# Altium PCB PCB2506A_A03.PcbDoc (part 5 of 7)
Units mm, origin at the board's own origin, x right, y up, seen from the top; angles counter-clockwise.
Board outline 115 x 60 mm, 6 copper layers (Top Layer, Signal Layer 2, Signal Layer 3, Signal Layer 4, Signal Layer 5, Bottom Layer), stack 1.555 mm thick; 376 components, 290 nets, 1297 pads, 901 vias.
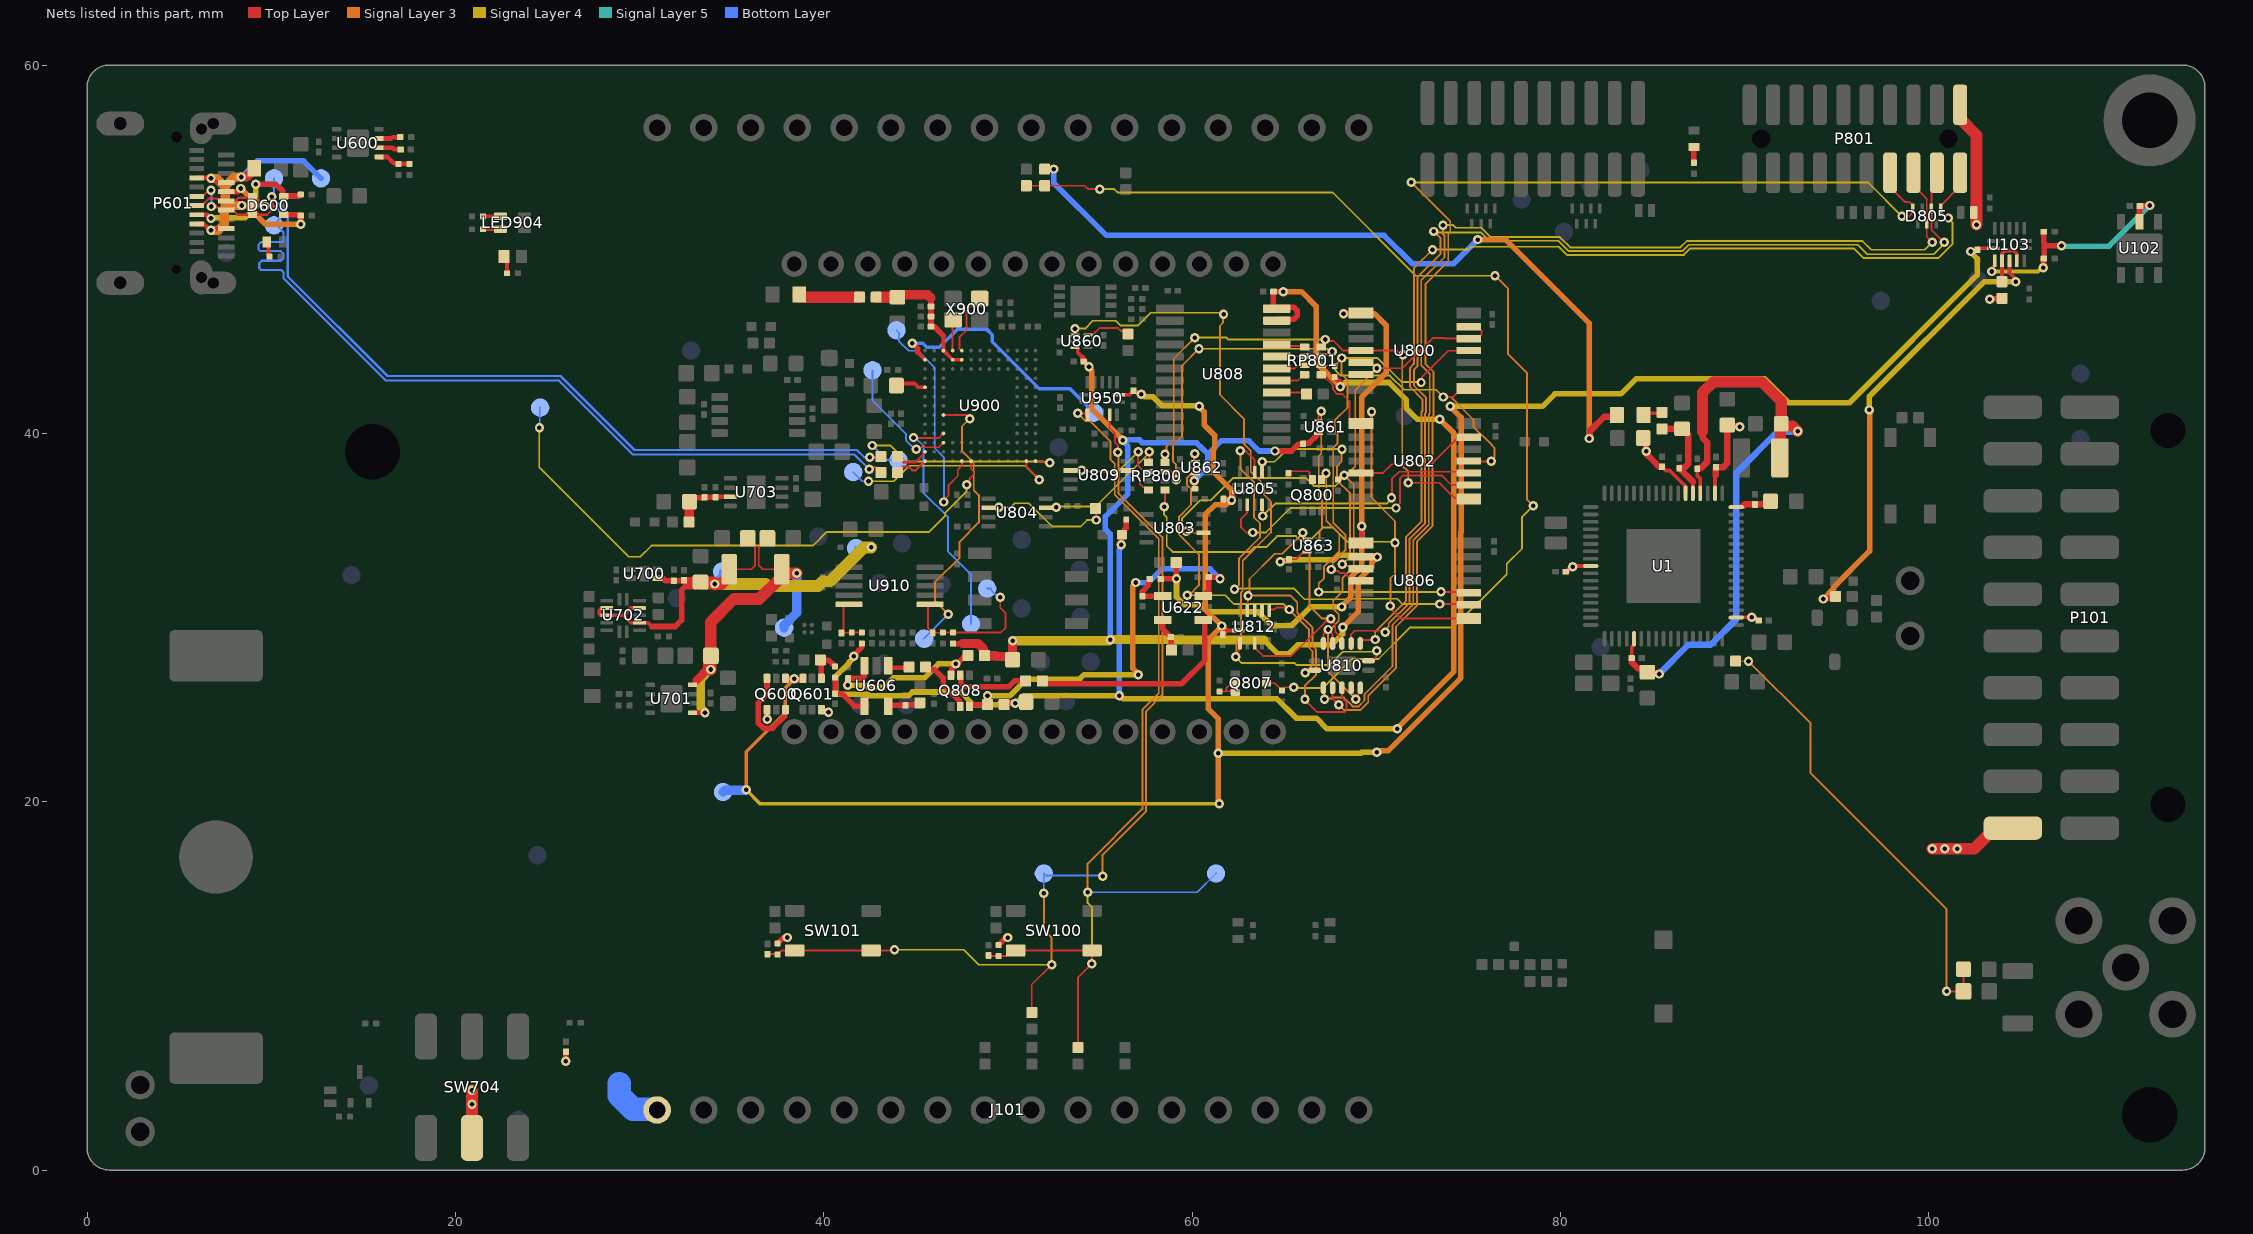
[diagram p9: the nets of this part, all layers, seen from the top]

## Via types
v1: diameter 0.508, hole 0.25, Top Layer to Bottom Layer, tented both sides, 901 vias

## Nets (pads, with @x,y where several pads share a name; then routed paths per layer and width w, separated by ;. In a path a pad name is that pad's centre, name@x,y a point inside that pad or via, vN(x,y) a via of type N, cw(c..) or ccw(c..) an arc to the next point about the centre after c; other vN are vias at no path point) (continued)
N16846319: Q800.1 U806.10 | length 15.8
  Top Layer w0.1: Q800.1@67.033,37.527 67.033,37.547 67.171,37.685 67.171,37.741 v1(67.276,37.846) ; v1(73.519,31.394) 74.981,31.394 U806.10@75.025,31.35
  Signal Layer 3 w0.1: v1(66.878,31.386) 66.878,31.855 67.169,32.146 67.169,32.778 67.996,33.604 67.996,34.541 67.286,35.25 67.286,37.836 v1(67.276,37.846)
  Signal Layer 4 w0.1: v1(66.878,31.386) 66.882,31.39 73.515,31.39 v1(73.519,31.394)
N16846537: RP801.5 U808.21 | length 1.6
  Top Layer w0.1: U808.21@64.6,44.825 64.671,44.754 66.056,44.754 RP801.5@66.118,44.692
N16846539: RP801.6 U808.20 | length 1.5
  Top Layer w0.1: U808.20@64.6,44.175 64.617,44.192 RP801.6@66.118,44.192
N16846547: RP801.7 U808.19 | length 1.6
  Top Layer w0.1: U808.19@64.6,43.525 65.575,43.525 65.718,43.668 66.094,43.668 RP801.7@66.118,43.692
N16846551: RP801.8 U808.18 | length 1.6
  Top Layer w0.1: U808.18@64.6,42.875 65.751,42.875 66.068,43.192 RP801.8@66.118,43.192
N16846567: Q800.2 R815.1 | length 1.6
  Top Layer w0.1: R815.1@65.232,37.832 65.232,37.838 65.342,37.948 66.312,37.948 66.371,37.889 66.371,37.725 66.533,37.563 Q800.2@66.533,37.527
N16846723: R805.1 U808.17 | length 1.7
  Top Layer w0.1: U808.17@64.6,42.225 64.607,42.218 66.147,42.218 R805.1@66.226,42.139
N16846896: RP800.8 U809.3 | length 1.8
  Top Layer w0.1: U809.3@56.498,37.985 56.573,37.91 56.883,37.91 57.161,37.631 57.161,37.276 57.359,37.078 57.482,37.078 RP800.8@57.632,36.928
N16846900: RP800.6 U809.6 | length 5.6
  Top Layer w0.1: U809.6@53.398,37.985 53.401,37.988 54.013,37.988 v1(54.016,37.992) ; v1(57.074,39.014) 57.074,38.252 57.318,38.008 57.552,38.008 RP800.6@57.632,37.928
  Signal Layer 4 w0.1: v1(54.016,37.992) 54.072,37.936 55.995,37.936 v1(57.074,39.014)
N16846924: RP800.5 U804.3 | length 7.5
  Top Layer w0.1: U804.3@52.053,35.954 52.073,35.973 52.608,35.973 v1(52.628,35.993) ; RP800.5@57.632,38.428 57.682,38.478 v1(57.682,39.008)
  Signal Layer 4 w0.1: v1(52.628,35.993) 52.666,36.031 54.776,36.031 57.682,38.937 v1(57.682,39.008)
N16847739: U805.10 U806.9 | length 23.3
  Top Layer w0.1: v1(62.625,39.068) 62.9,39.068 63.4,38.568 U805.10@63.4,37.885 ; v1(73.457,30.734) 74.991,30.734 U806.9@75.025,30.7
  Signal Layer 3 w0.1: v1@62.309,31.55 62.554,31.795 62.554,33.217 63.69,34.353 63.69,35.116 63.373,35.433 63.373,37.338 62.625,38.086 v1(62.625,39.068)
  Signal Layer 4 w0.1: v1(62.306,31.547) 62.343,31.584 65.517,31.584 66.108,30.993 68.508,30.993 68.533,31.019 71.145,31.019 71.43,30.734 v1(73.457,30.734)
N16847741: U805.9 U806.3 | length 13.3
  Top Layer w0.1: v1(63.807,38.464) 63.804,38.461 63.804,37.798 U805.9@63.832,37.77 ; v1(68.154,32.887) 68.265,32.887 68.352,32.8 69.025,32.8 U806.3@69.175,32.65
  Signal Layer 3 w0.1: v1(68.146,39.146) 68.107,39.106 68.107,38.465 67.869,38.227 67.869,37.465 68.58,36.754 68.58,33.311 v1(68.154,32.887) v1(68.154,32.887)
  Signal Layer 4 w0.1: v1(63.807,38.464) 64.478,38.464 64.667,38.653 64.669,38.653 65.162,39.146 v1(68.146,39.146)
N16847743: U802.10 U805.4 | length 13.4
  Top Layer w0.1: U805.4@63.8,36.115 63.822,36.093 63.822,35.54 v1(63.843,35.518) ; v1(70.831,36.509) 70.854,36.531 70.854,37.529 71.246,37.921 74.954,37.921 U802.10@75.025,37.85
  Signal Layer 4 w0.1: v1(63.843,35.518) 64.515,36.19 70.576,36.19 70.831,36.445 v1(70.831,36.509)
N16847749: U802.9 U805.2 | length 16.4
  Top Layer w0.1: U805.2@63,36.355 62.99,36.345 62.99,35.685 62.662,35.357 62.662,34.9 62.941,34.62 v1(63.297,34.62) ; v1(71.074,35.951) 71.074,35.975 71.298,36.199 71.298,37.565 71.454,37.721 73.556,37.721 74.077,37.2 U802.9@75.025,37.2
  Signal Layer 4 w0.1: v1(63.297,34.62) 64.008,34.62 65.339,35.951 v1(71.074,35.951)
N16847975: R810.1 U804.6 | length 7.3
  Top Layer w0.1: U804.6@48.953,35.954 48.971,35.972 49.5,35.972 v1(49.518,35.99) ; R810.1@54.75,35.925 54.8,35.875 v1(54.8,35.3)
  Signal Layer 3 w0.1: v1(54.8,35.3) v1@54.825,35.3
  Signal Layer 4 w0.1: v1(49.518,35.99) 50.155,35.99 50.372,36.207 51.144,36.207 52.406,34.945 53.946,34.945 54.301,35.3 v1(54.8,35.3)
N16851964: C127.2 R128.2 R129.1 | length 25.2
  Top Layer w0.1: R129.1@89.523,27.638 89.537,27.624 v1(90.215,27.624) ; v1(100.972,9.7) R128.2@101.889,9.7 C127.2@101.889,10.9
  Signal Layer 3 w0.1: v1(90.215,27.624) 93.586,24.253 93.586,21.554 100.972,14.168 v1(100.972,9.7)
N16916520: U810.1 U812.1 U860.4 | length 39.6
  Top Layer w0.1: U860.4@53.5,45.35 53.62,45.35 53.645,45.375 v1(53.645,45.695) ; v1(62.372,27.868) 62.45,27.946 62.45,28.098 62.563,28.212 62.563,28.578 U812.1@62.6,28.615 ; U810.1@69.585,27.643 69.785,27.643 70.007,27.865 70.007,28.187 v1(70.024,28.204)
  Signal Layer 3 w0.1: v1(61.711,46.471) 61.678,46.437 61.678,46.006 61.519,45.847 61.519,42.099 62.817,40.8 62.817,39.431 63.189,39.059 63.189,37.928 63.906,37.21 63.906,36.667 64.287,36.286 64.287,34.626 62.754,33.093 62.754,31.458 62.65,31.354 62.65,28.843 62.409,28.601 62.409,27.905 v1(62.372,27.868)
  Signal Layer 4 w0.1: v1(53.645,45.695) 54.195,45.695 54.618,46.118 55.867,46.118 56.131,45.854 57.055,45.854 57.751,46.55 61.449,46.55 61.45,46.549 61.633,46.549 v1(61.711,46.471) ; v1(62.372,27.868) 62.372,27.86 62.707,27.524 65.575,27.524 65.667,27.432 67.474,27.432 68.185,28.143 69.964,28.143 v1(70.024,28.204)
N16916530: U810.4 U812.3 U861.4 | length 20
  Top Layer w0.1: U812.3@63.4,28.615 63.4,28.375 63.55,28.225 ; 63.55,28.225 63.86,27.915 65.383,27.915 67.223,29.755 67.234,29.755 67.351,29.873 67.463,29.873 67.466,29.87 67.615,29.87 67.615,29.777 67.779,29.613 67.779,29.227 68.062,28.944 68.062,28.921 68.135,28.847 U810.4@68.135,28.593 ; U861.4@66.873,40.693 66.873,40.958 67.013,41.098 v1(67.013,41.209) ; v1(67.529,29.942) v1@67.6,29.87
  Signal Layer 3 w0.1: v1(67.013,41.209) 67.013,38.891 66.883,38.761 66.883,36.574 67.056,36.401 67.056,34.849 66.924,34.717 66.924,34.26 66.384,33.719 66.384,30.619 67.061,29.942 v1(67.529,29.942)
N16916558: U810.11 U812.11 U863.4 | length 19
  Top Layer w0.1: U812.11@63,30.385 63.021,30.406 63.021,31.17 v1(63.043,31.191) ; v1(66.015,34.612) 66.036,34.59 66.036,34.288 66.061,34.263 U863.4@66.236,34.263 ; v1(66.131,25.571) 66.131,25.537 66.802,24.867 68.298,24.867 68.389,24.957 68.389,25.41 68.135,25.664 U810.11@68.135,26.193
  Signal Layer 3 w0.1: v1(66.015,34.612) 66.015,34.575 64.903,33.464 64.489,33.464 63.121,32.096 63.121,31.269 v1(63.043,31.191) 65.352,31.191 65.715,30.829 65.715,30.268 66.545,29.438 66.545,28.457 66.734,28.267 66.734,26.907 66.131,26.304 v1(66.131,25.571)
N16916616: U810.8 U812.8 U862.4 | length 21.1
  Top Layer w0.1: v1(60.139,38.887) 60.139,38.51 60.146,38.503 U862.4@60.173,38.503 ; U812.8@64.2,30.385 64.25,30.435 64.25,30.441 64.471,30.441 64.572,30.543 65.061,30.543 65.164,30.44 v1(65.272,30.44) ; v1(66.153,27.007) 66.264,27.007 66.362,27.105 66.647,27.105 U810.8@66.685,27.143
  Signal Layer 3 w0.1: v1(59.746,31.217) 59.846,31.217 60.376,31.747 60.376,33.426 59.297,34.505 59.297,35.484 59.819,36.005 59.944,36.131 59.944,36.982 59.81,37.116 59.729,37.197 59.729,37.602 60.096,37.97 60.096,38.844 v1(60.139,38.887) ; v1(65.272,30.44) 65.272,30.428 66.345,29.355 66.345,28.374 66.534,28.184 66.534,27.4 66.153,27.019 v1(66.153,27.007)
  Signal Layer 4 w0.1: v1(59.746,31.217) 61.795,31.217 62.277,30.734 64.978,30.734 v1(65.272,30.44)
N16917071: R882.1 U860.3 | length 2.5
  Top Layer w0.1: U860.3@54.35,45.35 54.375,45.375 54.646,45.375 54.996,45.725 55.977,45.725 56.134,45.568 56.357,45.568 R882.1@56.525,45.4
N16922979: R601.1 R602.2 U600.5 | length 1.8
  Top Layer w0.25: U600.5@15.85,55.013 16.31,55.013 16.643,54.68 16.865,54.68 R601.1@16.9,54.645 ; R601.1@16.9,54.635 R602.2@17.5,54.635
N16923003: R600.1 U600.7 | length 1.2
  Top Layer w0.25: U600.7@15.85,56.013 16.516,56.013 16.59,56.087 R600.1@17,56.087
N16923019: C602.1 U600.6 | length 1.2
  Top Layer w0.25: U600.6@15.85,55.513 16.598,55.513 16.689,55.422 17.014,55.422 C602.1@17.025,55.411
N16924927: Q600.3 Q600.6 | length 4.9
  Top Layer w0.3: Q600.6@36.919,26.7 36.919,25.845 36.439,25.364 36.439,24.281 36.727,23.993 37.226,23.993 37.882,24.648 Q600.3@37.882,25.053
N16934878: C900.1 U900.J13 | length 1.7
  Top Layer w0.2: C900.1@43.95,42.6 44.057,42.707 44.939,42.707 45.146,42.5 U900.J13@45.5,42.5
N16934900: C903.1 C904.1 C905.1 C906.1 R130.2 U900.M9 U900.M10 U900.N11 | length 7.5
  Top Layer w0.2: 46.5,45.3 U900.N11@46.5,44.5 U900.M10@47,44 U900.M9@47.5,44
  Top Layer w0.3: 45.825,47.35 C906.1@45.825,46.9 C905.1@45.825,46.35 C904.1@45.825,45.8 46,45.8 46.5,45.3
  Top Layer w0.5: C903.1@44,47.4 44.125,47.525 45.65,47.525 45.825,47.35
  Top Layer w0.635: R130.2@42.85,47.4 C903.1@44,47.4
N16936696: U900.N10 X900.1 | length 1.7
  Top Layer w0.1: U900.N10@47,44.5 47,46.15 X900.1@47.05,46.2
N16936699: U900.N9 X900.3 | length 3.2
  Top Layer w0.1: U900.N9@47.5,44.5 47.48,44.5 47.371,44.609 47.371,45.212 47.752,45.593 47.752,46.652 X900.3@48.3,47.2
N16938060: TPJ905.1 U900.M13 | length 13.7
  Top Layer w0.2: 45.1,44.4 U900.M13@45.5,44
  Top Layer w0.3: v1(44.8,44.9) 45.1,44.6 45.1,44.4
  Bottom Layer w0.2: v1(44.8,44.9) 45.374,44.9 45.595,44.679 46.279,44.679 47.249,45.649 48.865,45.649 49.149,45.364 49.149,44.983 51.707,42.425 53.379,42.425 TPJ905.1@54.678,41.126
N16939106: TPJ909.1 U900.C11 | length 6.7
  Top Layer w0.1: v1@45.25,39.25 46.25,39.25 U900.C11@46.5,39.5
  Bottom Layer w0.1: TPJ909.1@42.651,43.427 42.651,41.774 44.475,39.95 44.475,39.656 44.482,39.649 44.482,39.612 44.944,39.15 v1(45.025,39.15)
N16939109: TPJ910.1 U900.D11 | length 13.2
  Top Layer w0.1: v1(44.875,39.775) 44.9,39.75 46.25,39.75 U900.D11@46.5,40
  Bottom Layer w0.1: v1(44.875,39.775) 44.975,39.775 45.418,39.332 45.418,38.368 45.415,38.365 45.415,36.785 46.75,35.45 46.75,33.579 48.003,32.326 TPJ910.1@48.003,29.65
N16939489: TPJ911.1 U900.F11 | length 15.8
  Top Layer w0.1: U900.F11@46.5,41 47.725,41 v1(47.925,40.8)
  Signal Layer 3 w0.1: v1(46.761,30.175) 46.05,30.886 46.05,31.935 47.375,33.26 47.375,34.119 48.424,35.169 48.424,36.649 48.15,36.923 48.15,38.404 47.5,39.054 47.5,40.375 v1(47.925,40.8)
  Bottom Layer w0.1: TPJ911.1@45.453,28.85 45.453,28.867 v1(46.761,30.175)
N16939638: TPJ900.1 U900.A2 | length 12.3
  Top Layer w0.1: U900.A2@51,38.5 51.019,38.481 51.019,38.188 51.488,37.719 51.562,37.719 51.706,37.575 v1(51.706,37.477)
  Signal Layer 4 w0.1: v1(42.429,37.4) 43.8,37.4 44.646,38.246 50.937,38.246 v1(51.706,37.477)
  Bottom Layer w0.1: TPJ900.1@41.602,37.9 42.102,37.4 v1(42.429,37.4)
N16939640: TPJ901.1 U900.A1 | length 12.6
  Top Layer w0.1: U900.A1@51.5,38.5 51.519,38.481 51.59,38.481 51.592,38.478 51.922,38.478 51.922,38.476 52.019,38.379 52.255,38.379 v1(52.278,38.403)
  Signal Layer 4 w0.1: v1(42.631,39.346) 43.604,39.346 44.473,38.477 51.921,38.477 51.951,38.447 52.234,38.447 v1(52.278,38.403)
  Bottom Layer w0.1: v1(42.631,39.346) 43.426,38.55 TPJ901.1@44.053,38.55
N16940103: TPJ908.1 U900.A9 | length 13.3
  Top Layer w0.1: v1(46.525,36.275) 46.525,36.376 46.782,36.633 46.782,37.196 47.275,37.688 47.275,38.016 47.5,38.241 U900.A9@47.5,38.5
  Bottom Layer w0.1: TPJ908.1@43.952,45.601 44.085,45.468 44.085,45.015 44.607,44.493 45.107,44.493 46.025,43.575 46.025,39.208 46.525,38.708 v1(46.525,36.275)
N16942491: R902.2 U900.B13 | length 1.9
  Top Layer w0.12: R902.2@44,38.75 44.32,38.43 44.98,38.43 45.5,38.95 U900.B13@45.5,39
N16942503: R904.2 U900.A13 | length 1.9
  Top Layer w0.12: R904.2@44,37.875 44.325,38.2 44.6,38.2 44.8,38 45,38 U900.A13@45.5,38.5
N16943456: TPJ902.1 U900.A8 | length 31.9
  Top Layer w0.1: v1(47.757,37.209) 47.757,37.319 47.95,37.512 47.95,37.58 48.143,37.773 48.143,37.931 48,38.073 U900.A8@48,38.5
  Signal Layer 4 w0.1: v1(24.562,40.31) 24.551,40.299 24.551,38.173 29.419,33.306 30.044,33.306 30.647,33.909 39.416,33.909 40.157,34.65 45.721,34.65 46.6,35.529 46.6,35.7 47.757,36.857 v1(47.757,37.209)
  Bottom Layer w0.1: v1(24.562,40.31) 24.581,40.329 24.581,41.381 TPJ902.1@24.6,41.4
N16944010: LED903.2 R912.2 | length 1.1
  Top Layer w0.2: LED903.2@22.582,49.703 22.801,49.484 R912.2@22.801,48.688
N16996446: Q807.5 Q807.6 R838.1 | length 1.7
  Top Layer w0.1: R838.1@61.5,25.987 61.516,26.003 61.854,26.003 ; Q807.6@62.35,25.938 62.285,26.003 61.854,26.003 ; Q807.5@62.35,26.438 62.212,26.3 61.987,26.3 61.854,26.167 61.854,26.003
N17012885: L900.2 R130.1 | length 3.5
  Top Layer w0.635: L900.2@38.615,47.55 38.615,47.445 38.633,47.427 38.977,47.427 39.004,47.4 R130.1@41.95,47.4
N17065843: C15.1 C16.1 U1.51 | length 1.7
  Top Layer w0.2: C16.1@91.246,36.144 C16.1@91.418,36.316
  Top Layer w0.35: 89.971,36.075 89.937,36.075 90.005,36.143 C15.1@90.552,36.143 ; C15.1@90.507,36.144 C16.1@91.246,36.144
N17240604: LED904.2 R920.2 | length 0.9
  Top Layer w0.2: R920.2@21.501,51.789 LED904.2@22.451,51.789
N17240606: LED904.1 R919.2 | length 0.9
  Top Layer w0.2: R919.2@21.46,51.079 LED904.1@22.41,51.079
N17240618: LED901.1 R903.2 | length 0.9
  Top Layer w0.2: LED901.1@9.75,50.4 9.85,50.3 9.85,49.65 R903.2@9.9,49.6
N17240622: LED900.1 R900.2 | length 0.8
  Top Layer w0.3: R900.2@87.25,54.703 LED900.1@87.25,55.55
N17258791: C17.1 C18.1 R2.2 U1.56 | length 5.4
  Top Layer w0.2: U1.56@87.2,36.75 87.2,37.369
  Top Layer w0.35: R2.2@85.522,40.248 85.526,40.251 86.604,40.251 C17.1@86.608,40.255 86.633,40.255 86.944,39.943 86.944,38.339 86.739,38.134 86.547,38.134 C18.1@86.496,38.084 ; C18.1@86.455,38.114 87.2,37.369
N17258819: L1.2 R2.1 | length 1
  Top Layer w0.2: L1.2@84.587,40.972 84.712,41.097 R2.1@85.522,41.097
N17457277: R984.2 U103.2 U103.4 | length 2.9
  Top Layer w0.2: R984.2@103.981,48.237 103.988,48.244 U103.2@103.988,49.366 103.988,49.759 104.165,49.936 104.615,49.936 104.788,49.764 U103.4@104.788,49.366
N17523909: Q808.6 R674.1 R675.1 U606.3 | length 9.6
  Top Layer w0.3: v1(41.313,26.319) R674.1@41.313,26.7 42.092,26.7 42.211,26.819 U606.3@42.211,27.392 ; Q808.6@46.915,26.869 46.953,26.907 46.953,27.212 47.168,27.427 v1(47.168,27.483) 47.224,27.483 R675.1@47.606,27.865
  Signal Layer 4 w0.3: v1(41.313,26.319) 42.273,26.319 42.366,26.226 43.269,26.226 43.774,26.731 45.476,26.731 46.228,27.483 v1(47.168,27.483)
N17523935: Q808.2 R679.2 | length 3.1
  Top Layer w0.3: R679.2@45.529,27.315 45.679,27.165 46.035,27.165 46.478,26.722 46.478,26.543 46.482,26.539 46.482,26.366 47.353,25.496 47.353,25.43 47.378,25.405 47.378,25.269 Q808.2@47.411,25.237
N17523983: Q601.4 R628.1 R672.2 | length 1.9
  Top Layer w0.3: R628.1@39.819,27.7 39.869,27.65 Q601.4@39.869,26.7 ; R628.1@39.869,27.737 39.916,27.69 40.269,27.69 40.599,27.36 40.609,27.36 40.619,27.35 R672.2@40.619,27.34
N17523989: C621.1 R672.1 U606.4 | length 2.8
  Top Layer w0.25: R672.1@40.619,26.74 40.619,26.75 R672.1@40.654,26.785
  Top Layer w0.3: R672.1@40.619,26.74 C621.1@40.619,25.865 40.987,25.865 41.661,25.192 U606.4@42.211,25.192
N17524020: R679.1 U606.1 | length 1.1
  Top Layer w0.25: U606.1@43.511,27.242 43.548,27.279 44.592,27.279 R679.1@44.629,27.315
N17524076: C660.1 R681.1 U606.5 | length 1.9
  Top Layer w0.3: U606.5@43.511,25.342 43.511,25.284 43.561,25.234 C660.1@44.44,25.234 44.44,25.254 44.45,25.264 45.11,25.264 R681.1@45.216,25.37
N17524925: Q808.3 R687.1 R688.1 U622.3 | length 22.3
  Top Layer w0.3: Q808.3@47.915,25.169 47.915,25.232 47.953,25.269 48.123,25.269 48.129,25.275 R687.1@48.896,25.275 v1(48.896,25.755) ; U622.3@60.6,31.171 60.904,31.476 R688.1@60.904,32.2 61.424,32.2 v1(61.519,32.106)
  Signal Layer 3 w0.3: v1(56.947,31.902) 56.769,31.725 56.769,27.26 57.074,26.955 v1(57.074,26.899)
  Signal Layer 4 w0.3: v1(48.896,25.755) 50.108,25.755 51.013,26.66 53.896,26.66 54.135,26.899 v1(57.074,26.899)
  Bottom Layer w0.3: v1(56.947,31.902) 57.633,31.902 58.369,32.639 60.985,32.639 v1(61.519,32.106)
N17524951: Q808.5 R686.2 | length 4.2
  Top Layer w0.3: Q808.5@47.415,26.869 47.434,26.851 47.434,26.441 47.627,26.248 50.056,26.248 50.367,26.559 R686.2@50.968,26.559
N17524994: C653.1 R629.1 U622.4 | length 2.2
  Top Layer w0.3: R629.1@57.7,32.1 57.7,31.97 57.633,31.902 57.633,31.761 57.3,31.428 C653.1@57.3,31.161 58.39,31.161 U622.4@58.4,31.171
N17525025: R686.1 U622.1 | length 11.6
  Top Layer w0.3: R686.1@51.868,26.559 52.018,26.409 52.19,26.409 52.194,26.406 59.426,26.406 60.693,27.673 U622.1@60.693,29.871
N17525073: C652.1 R690.1 U622.5 | length 1.9
  Top Layer w0.3: U622.5@58.4,29.871 58.419,29.852 58.419,29.372 58.817,28.975 58.817,28.955 58.827,28.945 58.856,28.945 58.866,28.935 58.866,28.248 R690.1@58.885,28.228
SI_HEADER_ENABLE: R807.2 U800.5 U800.6 U800.12 U800.13 U802.5 U802.13 U803.6 U810.5 U810.6 U810.12 U810.13 | length 53.2
  Top Layer w0.1: v1(59.69,34.696) 59.787,34.599 U803.6@60.621,34.599 ; U810.6@67.135,28.593 67.135,29.086 v1@67.386,29.337 ; v1(67.386,29.351) v1@67.386,29.337 ; U810.5@67.635,28.593 67.635,29.088 v1@67.386,29.337 ; R807.2@67.92,37.494 67.92,37.504 68.03,37.614 68.146,37.614 v1(68.262,37.73) 69.055,37.73 U802.5@69.175,37.85 70.362,37.85 70.84,38.329 73,38.329 74.321,39.65 74.875,39.65 U802.13@75.025,39.8 ; U810.12@68.635,26.193 68.635,25.939 v1@68.885,25.689 ; v1(68.885,25.571) v1@68.885,25.689 ; U810.13@69.135,26.193 69.135,25.939 v1@68.885,25.689 ; U800.6@69.175,43.2 69.65,43.2 69.929,43.479 v1@70.098,43.479 ; U800.5@69.175,43.85 69.325,43.7 69.896,43.7 69.917,43.679 70.012,43.679 v1@70.155,43.536 ; v1(70.041,43.536) v1@70.098,43.479 ; U800.13@75.025,45.8 75.5,45.8 75.717,45.583 75.717,45.367 75.587,45.237 75.112,45.237 U800.12@75.025,45.15 73.743,45.15 73.719,45.173 73.062,45.173 71.425,43.536 v1@70.155,43.536 ; v1@70.098,43.479 v1@70.155,43.536
  Signal Layer 3 w0.1: v1(68.885,25.571) 67.386,27.07 v1(67.386,29.351) 67.493,29.351 67.97,29.828 67.97,30.175 67.67,30.475 67.67,30.917 68.165,31.412 68.165,32.145 68.783,32.763 68.783,37.208 v1(68.262,37.73) 68.372,37.73 68.859,38.217 68.859,42.354 v1(70.041,43.536)
  Signal Layer 4 w0.1: v1(59.69,34.696) 59.69,34.728 59.461,34.956 59.461,35.382 60.452,36.373 61.008,36.373 62.211,37.576 66.192,37.576 66.631,37.137 67.764,37.137 68.262,37.634 v1(68.262,37.73)
SI_VCOM_CTS: D805.4 P801.8 U810.10 | length 65.2
  Top Layer w0.1: U810.10@67.635,26.193 67.635,25.586 v1(67.962,25.259) ; P801.8@97.905,54.158 97.905,53.37 98.7,52.575 98.95,52.575 99.15,52.375 D805.4@99.15,52.215 99.15,52 98.95,51.8 v1(98.55,51.8)
  Signal Layer 3 w0.1: v1(67.962,25.259) 67.984,25.259 68.265,24.978 69.13,24.978 69.566,25.414 69.566,25.748 71.085,27.266 71.085,29.516 72.214,30.645 72.214,34.12 73.055,34.96 73.055,40.92 73.112,40.977 73.112,43.347 72.669,43.79 72.669,48.108 73.911,49.349 73.911,50.826 74.022,50.937 74.022,51.53 v1(71.907,53.645)
  Signal Layer 4 w0.1: v1(71.907,53.645) 71.927,53.625 96.725,53.625 v1(98.55,51.8)
SI_VCOM_RTS: D805.6 P801.6 U810.9 | length 62.8
  Top Layer w0.1: U810.9@67.126,26.003 67.164,25.965 67.164,25.6 v1(67.194,25.571) ; P801.6@99.175,54.158 99.175,53.475 99.9,52.75 D805.6@99.9,51.385 99.9,50.675 v1(100.2,50.375)
  Signal Layer 3 w0.1: v1(67.194,25.571) 67.225,25.602 67.598,25.602 67.648,25.652 68.248,25.652 68.722,25.178 69.048,25.178 69.366,25.497 69.366,25.83 70.885,27.349 70.885,29.599 72.014,30.728 72.014,34.202 72.855,35.043 72.855,41.003 72.912,41.06 72.912,43.239 72.447,43.704 72.447,48.317 73.711,49.581 73.711,50.724 73.629,50.805 v1(73.629,51.311)
  Signal Layer 4 w0.1: v1(73.629,51.311) 74.176,51.311 74.318,51.169 75.711,51.169 76.219,50.66 79.966,50.66 80.529,50.098 86.521,50.098 86.874,50.45 96.4,50.45 96.875,49.975 99.8,49.975 v1(100.2,50.375)
SI_VCOM_RXD: D805.1 P801.2 U810.2 | length 57.8
  Top Layer w0.1: U810.2@69.135,28.593 69.135,28.643 69.227,28.735 69.227,28.775 69.913,28.775 v1(69.945,28.807) ; v1(101.075,51.7) 101,51.7 100.65,52.05 D805.1@100.65,52.215 100.65,52.375 101.715,53.44 P801.2@101.715,54.158
  Signal Layer 3 w0.1: v1(69.945,28.807) 69.945,29.226 70.322,29.603 71.614,30.894 71.614,34.368 72.455,35.209 72.455,41.169 72.512,41.226 72.512,41.853 71.844,42.52 71.844,43.571 72.047,43.774 72.047,48.972 v1(73.058,49.983)
  Signal Layer 4 w0.1: v1(73.058,49.983) 74.984,49.983 75.135,50.134 79.914,50.134 80.35,49.698 86.706,49.698 87.053,50.045 95.93,50.045 96.447,49.528 100.539,49.528 101.303,50.293 101.303,51.439 101.075,51.667 v1(101.075,51.7)
SI_VCOM_TXD: D805.2 P801.4 U810.3 | length 59.2
  Top Layer w0.1: U810.3@68.635,28.593 68.635,29.087 68.834,29.286 70.409,29.286 v1(70.485,29.21) ; P801.4@100.445,54.158 100.15,53.863 D805.2@100.15,52.215 100.15,51.05 100.811,50.389 v1(100.843,50.389)
  Signal Layer 3 w0.1: v1(70.485,29.21) 70.485,29.32 70.685,29.52 70.685,29.682 71.814,30.811 71.814,34.285 72.655,35.126 72.655,41.086 72.712,41.143 72.712,41.936 72.044,42.603 72.044,43.469 72.247,43.672 72.247,48.498 73.5,49.751 73.5,50.596 v1(73.127,50.969)
  Signal Layer 4 w0.1: v1(73.127,50.969) 73.178,50.918 74.495,50.918 74.497,50.92 75.677,50.92 76.136,50.46 79.883,50.46 80.446,49.898 86.623,49.898 86.97,50.245 96.155,50.245 96.672,49.728 100.278,49.728 100.843,50.293 v1(100.843,50.389)
TCK_SWCLK: RP800.3 RP801.3 U800.8 U802.11 | length 32
  Top Layer w0.1: RP800.3@58.532,37.928 58.897,37.928 59.058,37.767 59.058,37.563 v1(59.136,37.485) ; RP801.3@67.018,44.192 67.118,44.292 67.346,44.292 67.504,44.45 v1(67.615,44.45) ; v1(73.64,41.98) 74.18,41.98 74.65,42.45 U800.8@75.025,42.45 ; U802.11@75.025,38.5 75.044,38.481 v1(76.246,38.481)
  Signal Layer 3 w0.1: v1(59.136,37.485) 59.136,38.302 58.961,38.477 58.961,39.348 59.461,39.848 59.461,43.688 v1(60.376,44.602) ; v1(73.64,41.98) 74.057,41.98 75.282,40.756 75.282,40.357 76.291,39.348 76.291,39.344 76.429,39.206 76.429,38.744 76.246,38.561 v1(76.246,38.481)
  Signal Layer 4 w0.1: v1(60.376,44.602) 67.352,44.602 67.504,44.45 v1(67.615,44.45) 67.586,44.421 67.586,43.644 68.087,43.143 70.743,43.143 71.513,42.373 73.248,42.373 v1(73.64,41.98)
TDI: RP800.1 RP801.1 U802.1 U806.8 | length 37.7
  Top Layer w0.1: v1(58.499,36.013) 58.532,36.046 RP800.1@58.532,36.928 ; RP801.1@67.018,43.192 67.068,43.192 67.658,42.603 67.658,42.369 67.888,42.139 68.17,42.139 68.55,41.759 68.55,40.8 68.8,40.55 U802.1@69.175,40.55 69.327,40.702 69.651,40.702 69.748,40.8 v1(69.748,41.173) ; v1(70.771,30.626) 70.771,30.516 71.187,30.099 71.187,30.091 71.329,29.95 U806.8@75.025,29.95
  Signal Layer 3 w0.1: v1(69.748,41.173) 69.748,36.503 71.021,35.231 71.021,34.135 v1@71.095,34.061 ; v1(70.771,30.626) 70.778,30.634 70.778,32.145 71.021,32.387 71.021,33.988 v1@71.095,34.061 ; v1(71.021,34.061) v1@71.095,34.061
  Signal Layer 4 w0.1: v1(58.499,36.013) 58.471,35.985 58.471,35.611 58.623,35.458 58.623,33.888 58.944,33.567 63.125,33.567 63.388,33.83 64.026,33.83 64.621,34.425 65.645,34.425 65.923,34.148 66.355,34.148 67.094,34.886 67.668,34.886 68.437,34.118 70.964,34.118 v1(71.021,34.061)
TDO_SWO: R801.1 RP801.2 U800.11 U806.4 | length 24.2
  Top Layer w0.1: RP801.2@67.018,43.692 67.031,43.679 67.739,43.679 R801.1@67.752,43.667 67.752,43.677 68.123,44.047 v1(68.123,44.094) ; v1(67.562,32.614) 67.64,32.536 67.921,32.536 68.031,32.426 68.274,32.426 68.7,32 U806.4@69.175,32 ; v1(72.437,42.766) 72.494,42.823 72.494,43.081 73.903,44.49 75.015,44.49 U800.11@75.025,44.5
  Signal Layer 3 w0.1: v1(67.562,32.614) 67.64,32.692 67.64,32.966 68.326,33.652 68.326,34.493 67.669,35.151 67.669,39.224 67.906,39.461 67.906,40.007 67.753,40.16 67.753,40.705 68.443,41.396 68.443,42.885 68.123,43.205 v1(68.123,44.094)
  Signal Layer 4 w0.1: v1(68.123,44.094) 70.075,44.094 71.374,42.795 72.408,42.795 v1(72.437,42.766)
TMS_SWDIO: RP800.4 RP801.4 U800.4 U802.8 | length 30.5
  Top Layer w0.1: RP800.4@58.532,38.428 v1(58.532,38.872) ; RP801.4@67.018,44.692 67.058,44.692 67.148,44.782 67.208,44.842 67.208,44.911 67.238,44.94 v1(67.238,45.099) ; v1@67.222,44.896 67.347,45.021 67.499,45.021 67.5,45.02 67.696,45.02 68.216,44.5 U800.4@69.175,44.5 69.18,44.495 71.129,44.495 71.344,44.28 v1(71.455,44.28) ; v1(71.741,37.324) 73.42,37.324 74.259,36.485 74.99,36.485 U802.8@75.025,36.45
  Signal Layer 3 w0.1: v1(58.532,38.872) 58.607,38.947 58.607,39.276 59.004,39.674 59.004,44.069 60.135,45.2 v1(60.147,45.2) ; v1(71.455,44.28) 71.418,44.243 71.418,38.863 71.425,38.856 71.425,38.252 71.741,37.937 v1(71.741,37.324)
  Signal Layer 4 w0.1: v1(60.147,45.2) 60.159,45.212 61.861,45.212 61.974,45.099 v1@67.237,45.099
UIF_BUTTON0: C102.1 R100.1 R305.2 SW100.3 SW100.4 TPJ652.1 U950.8 | length 52.8
  Top Layer w0.1: C102.1@48.95,11.649 48.975,11.624 R100.1@49.5,11.624 49.952,11.624 50.254,11.925 SW100.3@50.425,11.925 SW100.4@54.575,11.925 54.575,11.217 v1(54.559,11.201) 53.8,10.442 R305.2@53.8,6.65 ; v1(53.8,41.088) 54.253,41.088 U950.8@54.325,41.015
  Signal Layer 3 w0.1: v1(53.8,41.088) 54.22,40.668 54.467,40.668 55.581,39.554 55.581,38.572 55.805,38.347 55.805,36.676 58.191,34.29 58.191,25.883 57.302,24.994 57.302,19.609 54.331,16.637 v1(54.331,15.088)
  Signal Layer 4 w0.1: v1(54.331,15.088) 54.331,14.503 54.559,14.275 v1(54.559,11.201)
  Bottom Layer w0.1: v1(54.331,15.088) 60.288,15.088 TPJ652.1@61.303,16.102
UIF_BUTTON1: C103.1 R101.1 R307.2 SW101.3 SW101.4 TPJ653.1 U950.11 | length 54.9
  Top Layer w0.1: C103.1@36.95,11.725 37.475,11.725 R101.1@37.5,11.7 37.725,11.925 SW101.3@38.425,11.925 SW101.4@42.575,11.925 43.802,11.925 v1(43.84,11.963) ; R307.2@51.3,8.55 51.3,10.076 v1(52.375,11.151) ; U950.11@55.525,41.015 55.525,40.294 55.801,40.017 55.801,39.951 55.81,39.942 55.81,39.514 55.976,39.348 55.976,38.989 v1(55.974,38.986)
  Signal Layer 3 w0.1: v1(51.943,15.037) 51.962,15.018 51.962,13.037 52.375,12.624 v1(52.375,11.151) ; v1(55.143,15.951) 55.143,17.12 57.506,19.482 57.506,24.914 58.391,25.8 58.391,34.373 56.005,36.759 56.005,38.955 v1(55.974,38.986)
  Signal Layer 4 w0.1: v1(43.84,11.963) 47.6,11.963 48.412,11.151 v1(52.375,11.151)
  Bottom Layer w0.1: v1(51.943,15.037) 51.948,15.042 51.948,15.942 TPJ653.1@52.005,15.999 ; TPJ653.1@51.953,16.102 51.953,16.051 TPJ653.1@52.005,15.999 ; v1(55.143,15.951) 55.095,15.999 TPJ653.1@52.005,15.999
USB_DM: D600.6 P601.A7 P601.B7 R902.1 TPJ612.1 | length 48.1
  Top Layer w0.12: P601.B7@5.95,52.875 6.275,52.875 6.6,53.2 v1(6.725,53.2) ; v1@6.75,52.35 7,52.35 7.225,52.125 P601.A7@7.55,52.125 7.925,52.125 8.175,51.875 D600.6@8.975,51.875 9.778,51.875 10.075,52.172 10.075,52.8 v1(10.025,52.85) ; v1(42.5,38.7) 43.05,38.7 R902.1@43.1,38.75
  Bottom Layer w0.12: v1@6.725,53.15 6.75,53.125 v1@6.75,52.35 ; TPJ612.1@10.15,53.85 10.15,52.975 v1(10.025,52.85) 10.9,51.975 10.9,48.525 16.31,43.115 25.71,43.115 27.55,41.275 29.725,39.1 41.8,39.1 42.2,38.7 v1(42.5,38.7)
  other v1: 6.75,52.325
USB_DP: D600.4 P601.A6 P601.B6 R904.1 TPJ611.1 | length 51.1
  Top Layer w0.12: P601.B6@5.95,52.375 6.225,52.375 6.6,52.75 7.075,52.75 7.2,52.625 P601.A6@7.55,52.625 8.05,52.625 8.225,52.8 8.775,52.8 8.85,52.875 D600.4@8.975,52.875 9.138,52.875 9.65,52.363 v1(9.65,52.35) ; v1(42.475,38.05) 42.475,38.173 42.477,38.175 42.8,38.175 R904.1@43.1,37.875
  Bottom Layer w0.12: v1(9.65,52.35) 10.175,52.35 10.55,51.975 10.55,51.762 10.15,51.362 TPJ611.1@10.15,51.3 10.291,51.3 10.66,50.931 10.66,50.47 10.59,50.4 9.45,50.4 9.3,50.25 9.3,49.997 9.397,49.9 10.516,49.9 10.66,49.756 10.66,49.51 10.525,49.375 9.475,49.375 9.347,49.247 9.347,48.967 9.438,48.875 10.53,48.875 10.66,48.745 10.66,48.426 16.211,42.875 25.611,42.875 27.38,41.105 29.626,38.86 41.665,38.86 v1(42.475,38.05)
USBC_CC1: D600.1 P601.A5 R621.2 | length 6.7
  Top Layer w0.3: P601.A5@7.55,53.125 8.175,53.125 v1(8.35,53.3) ; D600.1@10.675,51.875 11.55,51.875 R621.2@11.6,51.825 v1(11.6,51.35)
  Signal Layer 3 w0.3: v1(8.35,53.3) 8.975,52.675 8.975,52.075 9.7,51.35 v1(11.6,51.35)
USBC_CC2: D600.3 P601.B5 R620.2 | length 7.7
  Top Layer w0.25: P601.B5@5.95,51.875 6.525,51.875 6.7,51.7 v1@6.725,51.7
  Top Layer w0.3: v1(9.15,53.525) 10.25,53.525 10.625,53.15 10.625,52.925 D600.3@10.675,52.875 10.693,52.893 11.5,52.893 11.5,52.875 R620.2@11.6,52.975
  Signal Layer 4 w0.3: v1@6.725,51.7 8.575,51.7 9.15,52.275 v1(9.15,53.525)
  other v1: 6.725,51.675
USBC_VBUS: D600.5 L600.1 P601.A4 P601.A9 P601.B4 P601.B9 TPJ613.1 | length 16.1
  Top Layer w0.25: P601.B4@5.95,51.375 6.323,51.375 6.725,50.973 v1(6.725,51.025) 6.725,51.05 6.925,51.05 7,51.125 P601.A9@7.55,51.125 ; P601.B9@5.95,53.875 6.7,53.875 v1(6.725,53.85) 6.825,53.85 7.05,53.625 P601.A4@7.55,53.625
  Top Layer w0.35: v1(8.4,52.375) D600.5@8.975,52.375
  Top Layer w0.5: v1(8.375,53.925) 8.66,53.925 L600.1@9.135,54.4
  Signal Layer 3 w0.5: v1(6.725,51.025) 7.125,51.025 7.45,51.35 7.45,52.2 7.625,52.375 ; v1(6.725,53.85) 7.025,53.85 7.5,53.375 ; v1(8.375,53.925) 8,53.925 7.5,53.425 7.5,53.375 ; v1(8.4,52.375) 7.625,52.375 ; 7.5,53.375 7.5,52.5 7.625,52.375
  Bottom Layer w0.3: v1(8.375,53.925) 9.25,54.8 11.75,54.8 TPJ613.1@12.7,53.85
V_ADC: R114.2 U103.3 | length 24.6
  Top Layer w0.2: U103.3@104.388,49.366 104.388,48.726 104.665,48.448 104.665,48.294 v1(104.724,48.235)
  Top Layer w0.3: v1(94.285,31.007) 94.325,31.047 94.847,31.047 R114.2@94.95,31.15
  Signal Layer 3 w0.3: v1(94.285,31.007) 94.847,31.57 94.847,31.652 96.799,33.604 96.799,41.25 v1(96.774,41.275)
  Signal Layer 4 w0.3: v1(96.774,41.275) 96.774,42.001 103.007,48.235 v1(104.724,48.235)
V_SENSOR: C110.1 R108.1 R109.1 U102.5 U103.1 | length 13.3
  Top Layer w0.2: v1(103.429,48.793) 103.488,48.852 103.488,49.026 103.588,49.126 U103.1@103.588,49.366
  Top Layer w0.3: v1(106.223,48.997) 106.236,49.01 106.236,49.49 106.246,49.5 R108.1@106.25,49.5 ; R109.1@106.25,50.95 106.25,50.341 106.391,50.2 107.204,50.2 v1(107.213,50.19) ; R108.1@106.27,49.51 106.27,50.2 ; U102.5@111.45,51.5 111.45,52.175 C110.1@111.525,52.25 ; C110.1@111.525,52.375 v1(112,52.375)
  Signal Layer 4 w0.2: v1(103.429,48.793) 105.936,48.793 106.139,48.997 v1(106.223,48.997)
  Signal Layer 5 w0.3: v1(107.213,50.19) 107.229,50.175 109.8,50.175 v1(112,52.375)
V_SW: C800.1 C828.1 C950.1 C952.1 Q600.4 Q601.6 TPJ608.1 U103.14 U805.14 U812.14 U950.14 | length 131.8
  Top Layer w0.2: U950.14@56.01,42.1 56.6,42.1 C950.1@56.825,42.325 56.825,42.305 56.885,42.245 v1@57.033,42.245 ; 61.869,29.3 U812.14@62.515,29.3 ; U805.14@62.242,36.717 62.325,36.8 U805.14@62.515,36.8 ; v1(102.296,49.881) 102.342,49.927 102.602,49.927 C952.1@102.648,49.973 102.648,49.991 102.708,50.051 U103.14@103.503,50.051
  Top Layer w0.25: v1@62.242,36.538 U805.14@62.242,36.717
  Top Layer w0.3: Q600.4@37.919,26.7 37.934,26.685 38.39,26.685 38.445,26.63 Q601.6@38.829,26.63 ; v1(61.62,29.54) 61.66,29.501 C828.1@61.66,29.09 ; C828.1@61.672,29.083 61.672,29.103 61.869,29.3 ; C800.1@61.707,36.436 61.707,36.416 61.717,36.406 62.112,36.406 v1(62.146,36.373)
  Signal Layer 3 w0.2: v1(35.789,20.65) 35.789,22.716 37.908,24.836 37.908,26.173 v1(38.405,26.67)
  Signal Layer 3 w0.3: v1(60.401,41.478) 60.401,41.422 60.655,41.168 60.655,40.47 61.232,39.893 61.232,39.213 61.146,39.127 61.146,37.939 62.146,36.939 v1@62.146,36.469 ; v1(61.478,19.898) 61.438,19.938 61.438,20.085 61.417,20.106 v1(61.417,22.631) 61.417,24.511 60.884,25.044 60.884,28.804 v1(61.62,29.54) 60.714,30.447 60.714,35.587 61.248,36.122 61.839,36.122 62.09,36.373 v1(62.146,36.373) ; v1(70.028,22.682) 70.068,22.722 70.215,22.722 70.251,22.758 70.635,22.758 74.605,26.728 74.605,34.633 74.614,34.642 74.614,40.868 v1(74.016,41.466)
  Signal Layer 4 w0.2: v1(35.789,20.65) 36.556,19.883 61.463,19.883 v1(61.478,19.898)
  Signal Layer 4 w0.3: v1(57.234,42.128) 57.29,42.128 57.426,41.992 57.881,41.992 58.369,41.504 60.376,41.504 v1(60.401,41.478) ; v1(61.417,22.631) 69.174,22.631 69.225,22.682 v1(70.028,22.682) ; v1(74.016,41.466) 79.028,41.466 79.708,42.146 79.712,42.146 83.294,42.146 84.126,42.978 91.088,42.978 92.404,41.662 95.688,41.662 102.626,48.6 102.626,49.495 102.296,49.825 v1(102.296,49.881)
  Bottom Layer w0.5: TPJ608.1@34.528,20.527 34.624,20.622 35.758,20.622 35.786,20.65 v1(35.789,20.65)
VCOM_CTS: U812.9
VCOM_ENABLE: Q807.2 R320.1 R324.2 R839.2 | length 61.1
  Top Layer w0.1: R324.2@51,53.45 R320.1@52,53.45 54.17,53.45 54.356,53.264 v1(54.991,53.264) ; Q807.2@64.022,26.438 Q807.2@64.05,26.438 64.497,26.438 R839.2@64.888,26.046 ; R839.2@64.888,26.036 R839.2@64.888,26.046 ; v1(65.532,26.213) 65.065,26.213 65.008,26.156 64.998,26.156 R839.2@64.888,26.046 ; v1(78.523,36.068) v1@78.574,36.068
  Signal Layer 3 w0.1: v1(76.454,48.561) 77.165,47.849 77.165,44.298 78.194,43.269 78.194,36.397 v1(78.523,36.068)
  Signal Layer 4 w0.1: v1(54.991,53.264) 55.778,53.264 55.956,53.086 67.629,53.086 72.154,48.561 v1(76.454,48.561) ; v1(65.532,26.213) 65.577,26.168 67.087,26.168 68.67,27.75 70.126,27.75 71.84,29.464 74.194,29.464 77.086,32.356 77.086,32.912 77.924,33.75 77.924,35.469 v1(78.523,36.068)
VCOM_RTS: U812.10
VCS: C710.1 C714.1 C728.1 R717.2 U703.7 | length 3.5
  Top Layer w0.25: C710.1@34.129,36.533 34.154,36.558 U703.7@34.929,36.558
  Top Layer w0.3: C714.1@32.711,36.296 32.918,36.503 33.519,36.503 33.529,36.513 C728.1@33.529,36.533 C710.1@34.129,36.533
  Top Layer w0.5: R717.2@32.684,35.195 32.697,35.209 32.697,36.283 C714.1@32.711,36.296
VDCDC: C3.1 C4.1 C12.1 C13.1 L11.2 U1.22 U1.55 | length 35.8
  Top Layer w0.2: C4.1@83.872,27.804 83.872,28.397 84,28.525 U1.22@84,28.85 ; C13.1@87.433,38.079 87.427,38.073 87.427,37.719 87.6,37.546 U1.55@87.6,36.75
  Top Layer w0.35: C4.1@83.872,27.804 83.877,27.799 83.877,27.58 84.203,27.254 84.5,27.254 C3.1@84.725,27.029 84.836,26.918 84.887,26.969 85.336,26.969 v1(85.366,26.938) ; C13.1@87.448,38.084 87.463,38.099 87.608,38.099 87.986,38.477 87.986,39.497 87.732,39.751 87.732,40.107
  Top Layer w0.6: 87.732,40.107 87.732,42.215 88.316,42.799 90.957,42.799 91.995,41.762 C12.1@91.995,40.525 ; L11.2@91.917,38.673 91.956,38.712 91.956,40.486 C12.1@91.995,40.525 ; v1(92.888,40.12) 92.608,40.4 92.095,40.4 91.995,40.5 C12.1@91.995,40.525
  Bottom Layer w0.35: v1(85.366,26.938) 86.952,28.524 88.163,28.524 89.56,29.921 89.56,37.871 91.779,40.09 92.858,40.09 v1(92.888,40.12)
VMCU: C1.1 C2.1 C5.1 C6.1 C9.1 C10.1 C706.1 D808.1 J101.1 L1.1 P101.2 P801.1 Q600.1 Q601.3 R100.2 R101.2 R320.2 R984.1 SW704.5 TP703.1 U1.9 U1.36 U1.53 U1.57 | length 76
  Top Layer w0.2: v1(80.67,32.758) 80.712,32.8 U1.9@81.65,32.8 ; C6.1@85.526,38.185 85.526,38.165 85.586,38.105 85.606,38.105 85.721,37.99 85.937,37.99 86.8,37.127 U1.57@86.8,36.75 ; U1.53@88.4,36.75 88.4,37.687 88.441,37.728 ; U1.36@89.55,30 89.561,30.011 v1@90.387,30.011 ; v1(90.399,30.023) 90.458,29.964 90.625,29.964 90.745,29.844 C2.1@90.765,29.844
  Top Layer w0.3: v1(26,5.9) 26,5.925 C706.1@26,6.425 ; Q600.1@36.919,25.09 Q600.1@36.919,25 36.919,24.498 v1(36.932,24.486) ; R101.2@37.5,12.3 37.825,12.625 v1(38.025,12.625) ; Q601.3@39.869,25.09 Q601.3@39.869,25 39.869,24.94 40.019,24.94 40.073,24.887 40.235,24.887 v1(40.257,24.864) ; R100.2@49.5,12.224 49.9,12.624 v1(49.987,12.624) ; R320.2@52,54.35 52.003,54.353 52.487,54.353 v1(52.49,54.356) ; C1.1@80.29,32.49 80.3,32.5 80.36,32.5 80.619,32.758 v1(80.67,32.758) ; C5.1@84.497,39.75 84.63,39.617 84.63,39.065 v1(84.669,39.026) ; v1(103.327,47.295) 103.348,47.316 R984.1@104.002,47.316
  Top Layer w0.35: v1(81.564,39.727) 81.586,39.748 81.586,40.107 82.377,40.899 82.973,40.899 L1.1@83.072,40.998 ; v1(84.669,39.026) 84.7,38.995 84.7,38.851 84.984,38.567 85.361,38.19 85.521,38.19 C6.1@85.526,38.185 ; 88.441,37.728 88.447,37.734 88.447,38.165 C9.1@88.452,38.17 ; C9.1@88.452,38.17 88.457,38.175 88.862,38.175 89.067,38.38 C10.1@89.067,40.456 ; C10.1@89.042,40.456 C10.1@89.067,40.456 ; v1(89.738,40.361) 89.708,40.391 89.132,40.391 C10.1@89.067,40.456 ; v1@90.387,30.011 v1(90.399,30.023)
  Top Layer w0.635: SW704.5@20.9,1.75 v1(20.9,3.575) v1(20.9,4.325) ; v1(100.2,17.45) v1(100.875,17.45) v1(101.55,17.45) 102.475,17.45 103.595,18.57 P101.2@104.57,18.57 ; P801.1@101.715,57.841 101.715,57.085 102.6,56.2 v1@102.6,51.35
  Signal Layer 3 w0.3: v1(75.514,50.527) 77.032,50.527 81.564,45.995 v1(81.564,39.727)
  Bottom Layer w0.3: v1(52.49,54.356) 52.49,53.604 55.345,50.749 70.434,50.749 71.958,49.225 74.213,49.225 v1(75.514,50.527) ; v1@81.524,39.767 v1(81.564,39.727)
  Bottom Layer w1.27: TP703.1@28.9,4.7 28.9,4.05 29.644,3.306 30.906,3.306 J101.1@30.95,3.262
  other v1: 102.6,51.325
VMCU_BUF: C625.1 C861.1 C863.1 C865.1 C867.1 R630.2 R675.2 U806.2 U860.6 U861.6 U862.6 U863.6 | length 68.1
  Top Layer w0.1: v1(60.122,37.44) 60.122,37.76 60.147,37.785 U862.6@60.173,37.785 ; v1(64.795,33.037) 64.859,33.101 65.192,33.101 C867.1@65.256,33.165 65.663,33.165 66.036,33.538 66.211,33.538 U863.6@66.236,33.563
  Top Layer w0.2: U860.6@53.8,44.625 53.8,44.396 54.075,44.121 ; v1(60.122,37.44) 60.14,37.421 60.14,37.013 C861.1@60.159,36.994
  Top Layer w0.3: R630.2@47.019,28.59 47.549,28.59 ; C863.1@54.075,43.93 54.075,44.121 ; C863.1@54.151,43.894 54.407,43.638 v1(54.407,43.612) ; v1(64.507,39.046) 65.411,39.046 65.78,39.415 66.026,39.415 66.046,39.435 66.046,39.475 66.354,39.475 66.773,39.893 U861.6@66.773,39.918
  Top Layer w0.4: U806.2@69.175,33.3 70.035,33.3 v1(70.048,33.287)
  Top Layer w0.5: 47.549,28.59 48.385,28.59 48.678,28.298 48.678,27.981 48.737,27.922 49.345,27.922 49.38,27.887 50.106,27.887 50.256,27.737 C625.1@50.256,27.712 v1(50.256,28.742)
  Signal Layer 3 w0.3: v1(54.407,43.612) 54.407,43.556 54.559,43.403 54.559,41.321 v1(56.245,39.635) ; v1(68.188,29.482) 69.014,30.308 69.014,32.004 69.748,32.738 69.748,32.973 70.048,33.272 v1(70.048,33.287)
  Signal Layer 4 w0.3: 63.906,28.778 64.66,28.024 65.234,28.024 65.746,28.536 67.602,28.536 68.17,29.105 68.17,29.464 v1(68.188,29.482) ; v1(64.795,33.037) 64.835,33.076 65.331,33.076 65.387,33.132 67.702,33.132 67.95,33.38 68.924,33.38 69.017,33.287 v1(70.048,33.287)
  Signal Layer 4 w0.5: v1(50.256,28.742) 55.486,28.742 55.548,28.804 59.14,28.804 59.165,28.778 63.906,28.778
  Bottom Layer w0.3: v1(55.55,28.804) 55.55,34.55 55.3,34.8 55.3,35.5 56.515,36.715 56.515,39.309 56.245,39.579 v1(56.245,39.635) ; v1@56.488,39.649 57.149,39.649 57.297,39.501 60.246,39.501 60.246,39.485 60.535,39.196 60.549,39.196 60.862,38.884 ; v1(60.122,37.44) 60.862,38.179 60.862,38.884 ; v1(64.507,39.046) 63.646,39.046 63.094,39.599 61.576,39.599 60.862,38.884
VMCU_R: R701.1 R702.2 R709.2 TP700.1 U701.1 U701.4 | length 20
  Top Layer w0.1: R709.2@36.943,34.3 36.943,34.26 36.474,33.791 36.474,32.842 36.693,32.624 R701.1@37.714,32.624
  Top Layer w0.25: U701.1@32.878,24.842 33.552,24.842 v1(33.553,24.841) ; U701.4@32.878,26.342 33.003,26.342 33.003,26.501 33.096,26.594
  Top Layer w0.45: 33.096,26.594 33.669,27.167 v1@33.847,27.167 ; v1@33.675,27.35 33.675,27.724 33.858,27.907 R702.2@33.875,27.924
  Top Layer w0.635: v1(33.858,27.178) R702.2@33.858,27.907 ; R702.2@33.875,27.924 33.875,28.04 33.858,28.057 33.858,29.743 35.128,31.013 36.504,31.013 37.607,32.117 R701.1@37.607,32.517 ; R701.1@37.822,32.41 v1(38.532,32.41)
  Signal Layer 4 w0.45: v1@33.558,24.852 33.524,24.886 33.524,24.911 33.325,25.111 33.325,26.635 33.858,27.168 v1(33.858,27.178)
  Bottom Layer w0.5: TP700.1@37.85,29.45 37.85,29.585 38.532,30.267 v1(38.532,32.41)
VMCU_S: C700.1 C701.1 R701.2 R710.2 R760.2 TP701.1 TP705.1 U700.3 U702.2 U702.4 U702.9 U702.10 | length 28.1
  Top Layer w0.1: R701.2@34.864,32.624 36.053,32.624 36.271,32.842 36.271,33.852 35.93,34.192 R710.2@35.859,34.192
  Top Layer w0.2: U702.9@28.226,30.519 27.942,30.519 27.825,30.402 27.825,30.182 27.888,30.119 U702.10@28.226,30.119 29.117,30.119 ; 29.537,29.719 29.137,30.119 29.537,30.519 U702.4@29.996,30.519 ; 29.557,29.719 U702.2@29.996,29.719 30.454,29.719 30.657,29.515 ; C700.1@33.036,31.681 C700.1@33.286,31.931
  Top Layer w0.3: 30.657,29.515 31.938,29.515 32.283,29.86 32.283,31.505 32.459,31.681 C700.1@33.036,31.681 ; U700.3@30.983,32.134 31.264,32.134 31.398,32 C701.1@32.401,32 ; C700.1@33.236,32.005 C700.1@33.311,31.931
  Top Layer w0.4: C701.1@32.411,32.005 C700.1@33.236,32.005
  Top Layer w0.635: v1(34.087,31.826) 34.467,31.826 34.864,32.224 R701.2@34.864,32.624
  Top Layer w0.7: C700.1@33.311,31.931 33.361,31.881 34.032,31.881 34.047,31.866 v1(34.087,31.826)
  Signal Layer 4 w0.635: v1(34.087,31.826) 36.843,31.826 36.949,31.72 39.706,31.72 39.953,31.968 40.357,31.968 42.2,33.81 v1(42.58,33.81)
  Bottom Layer w0.2: TP705.1@41.75,33.775 41.768,33.793 42.563,33.793 v1(42.58,33.81)
  Bottom Layer w0.3: v1(34.087,31.826) 34.127,31.866 34.127,31.962 34.475,32.311 TP701.1@34.475,32.5
VMCU_SENSE: C632.1 R630.1 R631.2 TP708.1 U910.6 | length 8.5
  Top Layer w0.1: U910.6@45.774,30.72 45.757,30.72 45.657,30.62 45.657,29.447 45.919,29.185 C632.1@45.919,29.165 ; C632.1@45.932,29.178 46.457,29.178 R631.2@46.469,29.19 R630.1@47.019,29.19 49.612,29.19 49.872,29.45 49.872,30.244 49.586,30.53 v1(49.586,31.111)
  Bottom Layer w0.1: TP708.1@48.875,31.575 49.1,31.575 49.1,31.486 49.475,31.111 v1(49.586,31.111)
VTARGET: R629.2 R691.1 U800.1 U806.1 | length 33.6
  Top Layer w0.3: R629.2@58.3,32.1 59.151,32.1 v1(59.157,32.106) 59.149,32.113 59.149,32.993 R691.1@59.142,33 ; v1(68.224,46.507) 68.246,46.529 69.154,46.529 U800.1@69.175,46.55 ; U806.1@69.175,34.05 69.215,34.09 v1(69.215,34.966)
  Signal Layer 3 w0.3: v1(68.123,30.578) 68.123,30.592 68.614,31.083 68.614,32.17 69.215,32.771 69.215,41.975 70.534,43.294 70.534,45.875 69.901,46.507 v1(68.224,46.507)
  Signal Layer 4 w0.3: v1(59.157,32.106) 59.157,31.109 59.567,30.698 60.48,30.698 60.874,30.304 63.588,30.304 64.335,29.557 65.403,29.557 66.424,30.578 v1(68.123,30.578)
VTARGET_BUF: C655.1 C806.1 L801.1 R636.2 R687.2 R801.2 R809.2 U808.23 U808.24 | length 83.2
  Top Layer w0.3: v1(41.633,27.895) 41.633,27.951 42.059,28.377 42.059,28.58 R636.2@42.069,28.59 ; R687.2@49.796,25.275 49.866,25.345 v1(50.395,25.345) 50.43,25.38 50.96,25.38 C655.1@50.995,25.415 ; v1(56.15,33.95) 56.15,34.35 56.1,34.4 L801.1@56.2,34.5 56.225,34.5 56.325,34.6 56.325,34.755 56.425,34.855 R809.2@56.425,35.325 ; U808.23@64.6,46.125 U808.23@64.6,46.125 64.627,46.101 64.726,46.2 65.534,46.2 65.71,46.376 65.71,46.685 65.545,46.85 64.675,46.85 U808.24@64.6,46.775 64.497,46.775 64.422,46.85 C806.1@64.422,47.703 64.423,47.702 64.938,47.702 v1(64.948,47.693) ; R801.2@67.752,43.067 67.762,43.057 67.762,43.047 68.011,42.798 68.011,42.571 v1(68.05,42.532)
  Signal Layer 3 w0.3: v1(64.948,47.693) 64.956,47.701 65.938,47.701 66.745,46.895 66.745,43.837 v1(68.05,42.532) ; v1(71.138,23.959) 71.138,23.985 74.205,27.051 74.205,34.798 74.214,34.808 74.214,40.01 v1(73.457,40.767)
  Signal Layer 4 w0.3: v1(41.633,27.895) 41.633,27.839 41.39,27.596 41.39,27.547 40.64,26.797 40.64,26.01 40.824,25.826 42.388,25.826 42.469,25.745 44.603,25.745 44.817,25.959 47.447,25.959 48.144,25.262 49.474,25.262 49.557,25.345 v1(50.395,25.345) 50.451,25.345 50.862,25.756 v1(56.058,25.756) 56.114,25.756 56.266,25.603 64.591,25.603 65.658,24.536 66.751,24.536 67.328,23.959 v1(71.138,23.959) ; v1(68.05,42.532) 68.096,42.532 68.33,42.766 70.696,42.766 71.626,41.836 71.626,41.384 72.242,40.767 v1(73.457,40.767)
  Bottom Layer w0.3: 56.057,31.72 56.057,33.71 56.11,33.763 56.11,33.91 v1(56.15,33.95) ; v1(56.058,25.756) 56.058,31.719
VTARGET_SENSE: C638.1 R636.1 R637.2 U910.5 | length 3
  Top Layer w0.1: U910.5@41.374,30.72 41.169,30.72 41.069,30.62 41.069,29.265 C638.1@40.969,29.165 40.982,29.178 41.507,29.178 R637.2@41.519,29.19 R636.1@42.069,29.19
